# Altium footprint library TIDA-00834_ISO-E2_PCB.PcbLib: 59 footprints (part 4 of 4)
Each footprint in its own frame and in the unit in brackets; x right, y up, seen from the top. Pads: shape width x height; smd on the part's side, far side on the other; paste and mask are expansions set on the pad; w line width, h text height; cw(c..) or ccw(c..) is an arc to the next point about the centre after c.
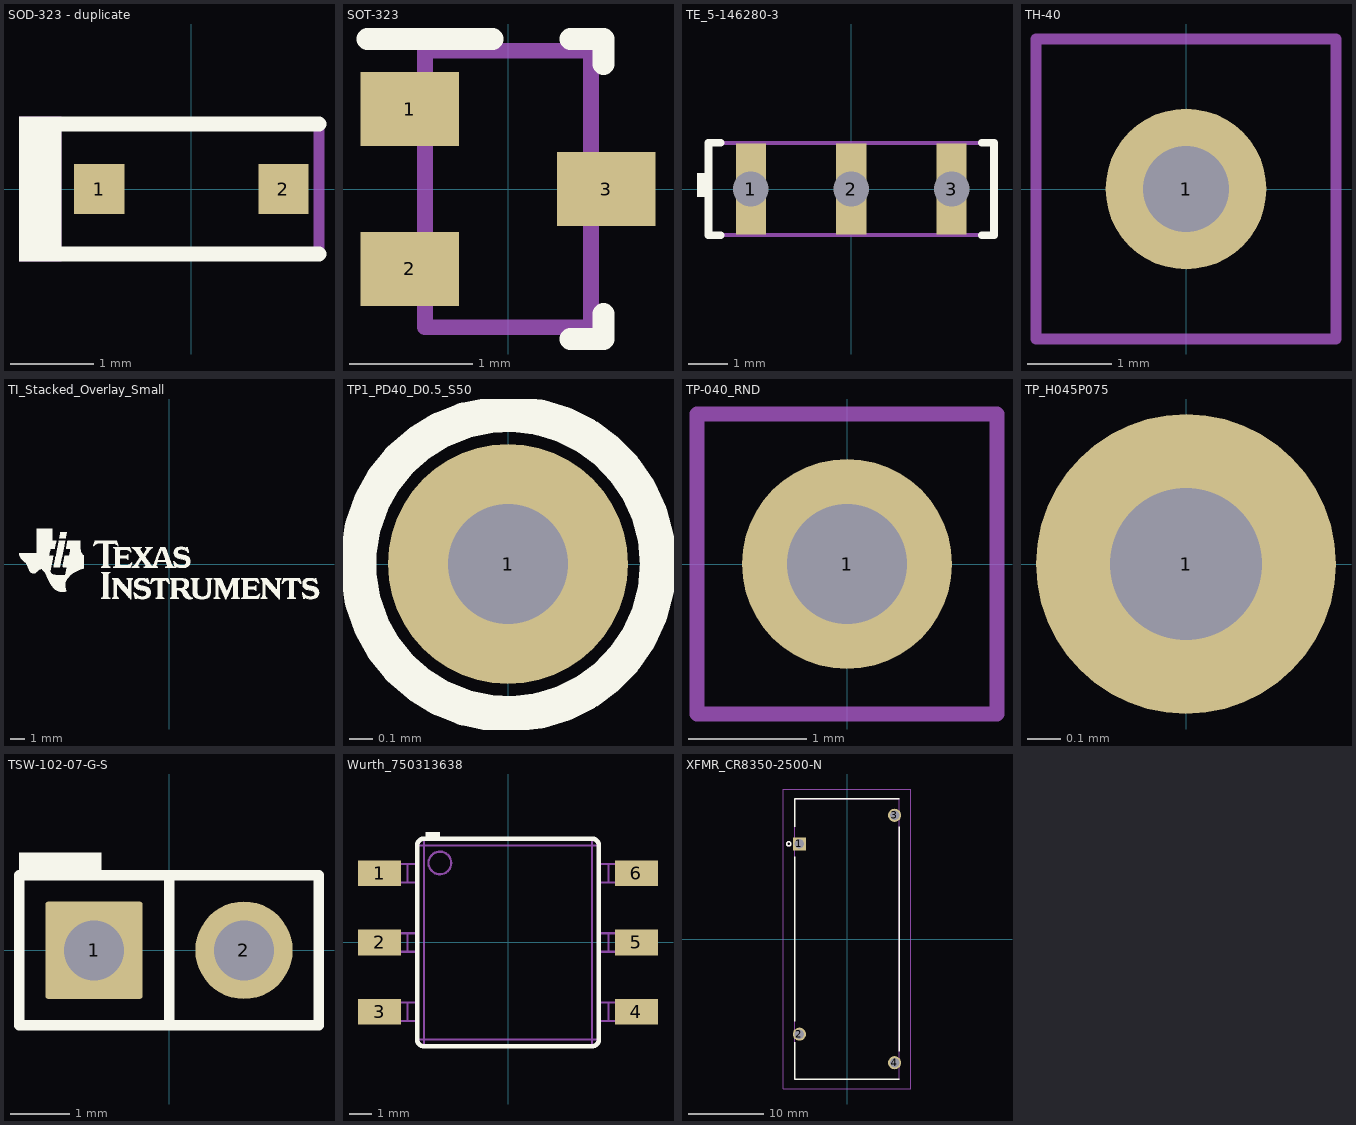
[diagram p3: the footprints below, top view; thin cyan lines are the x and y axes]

## SOD-323 - duplicate [mm]
pads (2):
  rect 0.6x0.6 smd: 1(-1.1,0) 2(1.1,0)
Top Overlay:
  rectangle: -2.057,-0.864 -1.549,0.864
  lines w0.178: -1.803,-0.775 0.1,-0.775 1.525,-0.775 ; -1.803,0.775 0.1,0.775 1.525,0.775
Mechanical 5:
  rectangle: -2.057,-0.864 -1.549,0.864
  lines w0.127: -1.803,-0.775 0.1,-0.775 1.525,-0.775 1.525,0.775 0.1,0.775 -1.803,0.775
  text ".Designator" at 0.737,0.279 h0.64
3D body "SOD-323.stp": height 1.1, standoff 0, extent -1.3,-0.675 1.3,0.675

## SOT-323 [mm] "Zetex recommended land pattern.  March 2007"
height 1.1
pads (3):
  rect 0.8x0.6 smd: 1(-0.8,0.65) 2(-0.8,-0.65) 3(0.8,0)
Top Overlay:
  lines w0.178: -1.143,1.219 -0.127,1.219 ; 0.508,-1.219 0.775,-1.219 0.775,-1.016 ; 0.508,1.219 0.775,1.219 0.775,1.016
Mechanical 5:
  lines w0.127: -1.125,-0.8 -0.975,-0.8 -0.935,-0.8 -0.884,-0.8 -0.725,-0.8 -0.675,-0.8 -0.675,-0.5 -0.725,-0.5 -0.884,-0.5 -0.935,-0.5 -0.975,-0.5 -1.125,-0.5 -1.125,-0.8 ; -1.125,0.5 -0.975,0.5 -0.935,0.5 -0.884,0.5 -0.725,0.5 -0.675,0.5 -0.675,0.8 -0.725,0.8 -0.884,0.8 -0.935,0.8 -0.975,0.8 -1.125,0.8 -1.125,0.5 ; -0.675,-1.125 0.675,-1.125 0.675,1.125 -0.675,1.125 -0.675,-1.125 ; 0.675,-0.15 0.675,0.15 0.725,0.15 0.884,0.15 0.935,0.15 0.975,0.15 1.125,0.15 1.125,-0.15 0.975,-0.15 0.935,-0.15 0.884,-0.15 0.725,-0.15 0.675,-0.15
  text ".Designator" at -0.376,0.754 h0.64
3D body "SC-70.stp": height 1.13, standoff 0.02, extent -1.125,-1.125 1.125,1.125

## TE_5-146280-3 [mm] "Header, 2.54mm, 3x1, TH"
height 8.72
pads (3):
  rect 0.76x2.29 hole 0.89: 1(-2.54,0) 2(0,0) 3(2.54,0)
Top Overlay:
  rectangle: -3.9,-0.2 -3.6,0.4
  lines w0.2: -3.3,-1.168 -3.607,-1.168 -3.607,1.169 -3.3,1.169 ; 3.3,-1.168 3.607,-1.168 3.607,1.169 3.3,1.169
Mechanical 5:
  lines w0.1: -3.607,-1.168 -3.607,1.169 3.607,1.169 3.607,-1.168 -3.607,-1.168 ; -2.851,-0.311 -2.851,0.311 -2.229,0.311 -2.229,-0.311 -2.851,-0.311
  text ".Designator" at 1.245,0.381 h0.64
3D body "c-5-146280-3-g-3d.stp": height 8.13, standoff -3.05, extent -3.607,-1.168 3.607,1.169

## TH-40 [mil]
pads (1):
  round 75 hole 40: 1(0,0)
Mechanical 5:
  lines w5: -70,-70 -70,70 70,70 70,-70 -70,-70
  text ".Designator" at -7,44 h25

## TI_Stacked_Overlay_Small [mm]
Top Overlay:
  drawing of 18 lines, arcs and shapes, not listed

## TP1_PD40_D0.5_S50 [mil]
height 1.4
pads (1):
  round 40 hole 20: 1(0,0)
Top Overlay:
  circle w6: c0,0 r25

## TP-040_RND [mil]
height 39.37
pads (1):
  round 70 / inner round 62 / far side round 62 hole 40: 1(0,0)
Mechanical 5:
  lines w5: -50,-50 50,-50 50,50 -50,50 -50,-50
  text ".Designator" at -42,65 h25

## TP_H045P075 [mil] "TP_H0.45P0.75"
height 104.33
pads (1):
  round 35 hole 17.72: 1(0,0)

## TSW-102-07-G-S [mm] "Samtec 100mil, 1x2, 230 mil above insulator"
height 8.382
pads (2):
  rrect6% 1.65x1.65 hole 1.016: 1(-1.27,0)
  round 1.65 hole 1.016: 2(1.27,0)
Top Overlay:
  rectangle: -2.54,1.27 -1.143,1.651
  lines w0.178: 0,-1.27 0,1.27 ; -2.54,-1.27 2.54,-1.27 2.54,1.27 -2.54,1.27 -2.54,-1.27
Mechanical 5:
  lines w0.127: -2.54,-1.27 -2.54,1.27 2.54,1.27 2.54,-1.27 -2.54,-1.27
  text ".Designator" at -1.524,-0.508 h0.64
3D body "SamtecTSW-07_2x1.stp": height 8.38, standoff -2.54, extent -2.54,-1.27 2.54,1.27

## Wurth_750313638 [mm] "SMD, 6-Leads, Body 8x9.14mm, Pitch 3.05mm"
height 7.62
pads (6):
  rect 1.9x1.14 smd: 1(-5.655,3.05) 2(-5.655,0) 3(-5.655,-3.05) 4(5.655,-3.05) 5(5.655,0) 6(5.655,3.05)
Top Overlay:
  rectangle: -3.625,4.57 -3,4.875
  lines w0.2: -4,-4.27 ccw(c-3.7,-4.27) -3.7,-4.57 3.7,-4.57 ccw(c3.7,-4.27) 4,-4.27 4,4.27 ccw(c3.7,4.27) 3.7,4.57 -3.7,4.57 ccw(c-3.7,4.27) -4,4.27 -4,-4.27
Mechanical 5:
  circle w0.1: c-3,3.5 r0.5
  lines w0.1: -4,-3.455 -4.43,-3.455 ; -4,-2.645 -4.43,-2.645 ; -4,-0.405 -4.43,-0.405 ; -4,0.405 -4.43,0.405 ; -4,2.645 -4.43,2.645 ; -4,3.455 -4.43,3.455 ; 4,-3.455 4.43,-3.455 ; 4,-2.645 4.43,-2.645 ; 4,-0.405 4.43,-0.405 ; 4,0.405 4.43,0.405 ; 4,2.645 4.43,2.645 ; 4,3.455 4.43,3.455 ; -5.47,-3.455 -5.376,-3.455 ; -5.47,-3.455 -6.35,-3.455 -6.35,-2.645 -5.47,-2.645 ; -5.47,-3.455 -5.47,-2.645 ; -5.47,-2.645 -5.376,-2.645 ; -5.47,-0.405 -6.35,-0.405 -6.35,0.405 -5.47,0.405 ; -5.47,-0.405 -5.376,-0.405 ; -5.47,-0.405 -5.47,0.405 ; -5.47,0.405 -5.376,0.405 ; -5.47,2.645 -5.376,2.645 ; -5.47,2.645 -6.35,2.645 -6.35,3.455 -5.47,3.455 ; -5.47,2.645 -5.47,3.455 ; -5.47,3.455 -5.376,3.455 ; -5.376,-3.455 -4.9,-3.455 ; -5.376,-3.455 -5.376,-2.645 ; -5.376,-2.645 -4.9,-2.645 ; -5.376,-0.405 -4.9,-0.405 ; -5.376,-0.405 -5.376,0.405 ; -5.376,0.405 -4.9,0.405 ; -5.376,2.645 -4.9,2.645 ; -5.376,2.645 -5.376,3.455 ; -5.376,3.455 -4.9,3.455 ; -4.9,-3.455 -4.43,-3.455 ; -4.9,-3.455 -4.9,-2.645 ; -4.9,-2.645 -4.43,-2.645 ; -4.9,-0.405 -4.43,-0.405 ; -4.9,-0.405 -4.9,0.405 ; -4.9,0.405 -4.43,0.405 ; -4.9,2.645 -4.43,2.645 ; -4.9,2.645 -4.9,3.455 ; -4.9,3.455 -4.43,3.455 ; -4.43,-3.455 -4.43,-2.645 ; -4.43,-0.405 -4.43,0.405 ; -4.43,2.645 -4.43,3.455 ; -4,-4.27 ccw(c-3.7,-4.27) -3.7,-4.57 ; -4,-4.27 -4,4.27 ; -4,-4.27 -3.7,-4.27 ; -4,4.27 cw(c-3.7,4.27) -3.7,4.57 ; -4,4.27 -3.7,4.27 ; -3.7,-4.57 3.7,-4.57 ; -3.7,-4.57 -3.7,-4.27 ; -3.7,-4.27 -3.7,4.27 ; -3.7,-4.27 3.7,-4.27 ; -3.7,4.27 3.7,4.27 ; -3.7,4.27 -3.7,4.57 ; -3.7,4.57 3.7,4.57 ; 3.7,-4.57 ccw(c3.7,-4.27) 4,-4.27 ; 3.7,-4.57 3.7,-4.27 ; 3.7,-4.27 3.7,4.27 ; 3.7,-4.27 4,-4.27 ; 3.7,4.27 3.7,4.57 ; 3.7,4.27 4,4.27 ; 3.7,4.57 cw(c3.7,4.27) 4,4.27 ; 4,-4.27 4,4.27 ; 4.43,-3.455 4.9,-3.455 ; 4.43,-3.455 4.43,-2.645 ; 4.43,-2.645 4.9,-2.645 ; 4.43,-0.405 4.9,-0.405 ; 4.43,-0.405 4.43,0.405 ; 4.43,0.405 4.9,0.405 ; 4.43,2.645 4.9,2.645 ; 4.43,2.645 4.43,3.455 ; 4.43,3.455 4.9,3.455 ; 4.9,-3.455 5.376,-3.455 ; 4.9,-3.455 4.9,-2.645 ; 4.9,-2.645 5.376,-2.645 ; 4.9,-0.405 5.376,-0.405 ; 4.9,-0.405 4.9,0.405 ; 4.9,0.405 5.376,0.405 ; 4.9,2.645 5.376,2.645 ; 4.9,2.645 4.9,3.455 ; 4.9,3.455 5.376,3.455 ; 5.376,-3.455 5.47,-3.455 ; 5.376,-3.455 5.376,-2.645 ; 5.376,-2.645 5.47,-2.645 ; 5.376,-0.405 5.47,-0.405 ; 5.376,-0.405 5.376,0.405 ; 5.376,0.405 5.47,0.405 ; 5.376,2.645 5.47,2.645 ; 5.376,2.645 5.376,3.455 ; 5.376,3.455 5.47,3.455 ; 5.47,-3.455 6.35,-3.455 6.35,-2.645 5.47,-2.645 ; 5.47,-3.455 5.47,-2.645 ; 5.47,-0.405 6.35,-0.405 6.35,0.405 5.47,0.405 ; 5.47,-0.405 5.47,0.405 ; 5.47,2.645 6.35,2.645 6.35,3.455 5.47,3.455 ; 5.47,2.645 5.47,3.455
  text ".Designator" at 0.673,0.206 h0.64
3D body "750313638.stp": height 7.62, standoff 0, extent -6.35,-4.57 6.35,4.57

## XFMR_CR8350-2500-N [mm] "CURRENT TRANSFORMERS, VERTICAL, 4 PIN, THRU"
height 39
pads (4):
  rect 1.754x1.754 / inner round 1.754 / far side rect 1.754x1.754 hole 1.254: 1(-6.35,12.7)
  round 1.754 hole 1.254: 2(-6.35,-12.7) 3(6.35,16.51) 4(6.35,-16.51)
Top Overlay:
  circle w0.178: c-7.76,12.7 r0.279
  lines w0.178: -7,-13.75 -7,-18.75 7,-18.75 ; -7,-11 -7,11 ; -7,15 -7,18.75 7,18.75 ; 7,-15 7,15
Bottom Overlay:
  lines w0.178: -7,-16.75 -7,-18.75 -5,-18.75 ; -7,-14.75 -7,-13.75 ; -7,-10.75 -7,-9.75 ; -7,-8.75 -7,-7.75 ; -7,-6.75 -7,-4.75 ; -7,-3 -7,-2 ; -7,-1 -7,0 ; -7,1 -7,3 ; -7,6 -7,7 ; -7,8 -7,9 ; -7,14.75 -7,15.75 ; -7,16.75 -7,18.75 -5,18.75 ; -6.985,3.937 -6.985,4.937 ; -6.985,10.033 -6.985,11.033 ; -3,-18.75 -2,-18.75 ; -3,18.75 -2,18.75 ; -1,-18.75 0,-18.75 ; -1,18.75 0,18.75 ; 1,-18.75 2,-18.75 ; 1,18.75 2,18.75 ; 3,-18.75 4,-18.75 ; 3,18.75 4,18.75 ; 5,-18.75 7,-18.75 7,-17.78 ; 5,18.75 7,18.75 7,17.653 ; 6.985,-12.684 6.985,-11.684 ; 6.985,4.08 6.985,5.08 ; 6.985,13.716 6.985,14.716 ; 7,-14.75 7,-13.75 ; 7,-10.75 7,-9.75 ; 7,-8.75 7,-7.75 ; 7,-6.75 7,-4.75 ; 7,-3 7,-2 ; 7,-1 7,0 ; 7,1 7,3 ; 7,6 7,7 ; 7,8 7,9 ; 7,10 7,12
Mechanical 5:
  circle w0.127: c-7.76,12.7 r0.279
  lines w0.127: -7,-18.75 -7,18.75 7,18.75 7,-18.75 -7,-18.75
  text ".Designator" at 0.61,-0.279 h0.64
Mechanical 15:
  lines w0.05: -8.497,-20.02 -8.497,20.02 8.497,20.02 8.497,-20.02 -8.497,-20.02
Mechanical 17:
  text "LEAD LENGTH IS 6MM" at -7.747,9.017 h1.05
3D body: height 39, standoff 0, extent -7,-18.75 7,18.75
